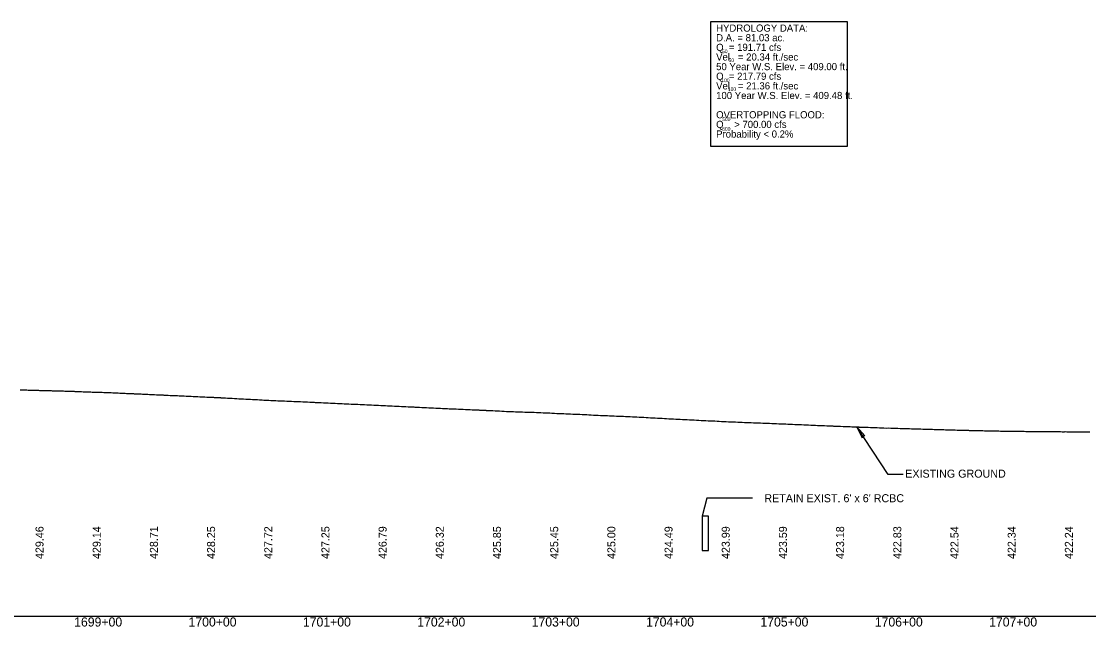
# Model space of a CAD drawing. Extents: x 2017200 to 2047700, y 854850 to 893350.
# Drawn here: x 2024830 to 2025763, y 856091 to 856620 of the extents above; entities that cross this region are included whole.
import ezdxf

# ---------------------------------------------------------------- set-up
doc = ezdxf.new("R2010")
doc.units = 0
for name, color, linetype in [('Culverts', 7, 'Continuous'), ('Default', 7, 'Continuous'), ('RD_DDB_Profile_EX', 7, 'Continuous'), ('RD_DDB_Profile_Lbl', 7, 'Continuous'), ('RD_DDB_StaTX', 7, 'Continuous'), ('RD_DDB_StripGrade', 7, 'Continuous'), ('RD_GPK_Profile_Cell', 7, 'Continuous'), ('RD_PD_DR_Pipe_TX', 7, 'Continuous'), ('RD_PD_Final_TX', 7, 'Continuous')]:
    doc.layers.add(name, color=color, linetype=linetype)

msp = doc.modelspace()

# ---------------------------------------------------------------- linework, layer by layer
at = {"layer": 'Culverts'}
for p, q in [((2025430.37, 856187.4), (2025424.78, 856187.4)), ((2025424.78, 856187.4), (2025424.78, 856157.4)), ((2025430.37, 856157.4), (2025430.37, 856187.4)), ((2025424.78, 856157.4), (2025430.37, 856157.4))]:
    msp.add_line(p, q, dxfattribs=at)
at = {"layer": 'Default'}
msp.add_lwpolyline([(2025432.39, 856620), (2025551.57, 856620), (2025551.57, 856510.68), (2025432.39, 856510.68)], close=True, dxfattribs=at)
at = {"layer": 'RD_DDB_Profile_EX'}
msp.add_lwpolyline([(2024828.51, 856297.92), (2024829.62, 856297.89), (2024830.51, 856297.88), (2024831.62, 856297.85), (2024832.5, 856297.81), (2024833.62, 856297.77), (2024834.5, 856297.76), (2024835.62, 856297.74), (2024836.5, 856297.7), (2024837.62, 856297.66), (2024838.5, 856297.65), (2024839.62, 856297.62), (2024840.5, 856297.59), (2024841.62, 856297.56), (2024842.51, 856297.54), (2024843.62, 856297.51), (2024844.52, 856297.48), (2024845.62, 856297.45), (2024846.54, 856297.44), (2024847.62, 856297.4), (2024848.55, 856297.36), (2024849.61, 856297.33), (2024850.56, 856297.31), (2024851.61, 856297.28), (2024852.56, 856297.25), (2024853.62, 856297.22), (2024854.55, 856297.19), (2024855.62, 856297.19), (2024856.54, 856297.16), (2024857.62, 856297.12), (2024858.53, 856297.12), (2024859.62, 856297.1), (2024860.52, 856297.06), (2024861.62, 856297.03), (2024862.5, 856297.02), (2024863.63, 856297), (2024864.47, 856296.97), (2024865.63, 856296.93), (2024866.45, 856296.91), (2024867.63, 856296.87), (2024868.42, 856296.84), (2024869.64, 856296.79), (2024870.39, 856296.78), (2024871.64, 856296.74), (2024872.37, 856296.7), (2024873.64, 856296.64), (2024874.35, 856296.62), (2024875.65, 856296.59), (2024876.33, 856296.56), (2024877.65, 856296.49), (2024878.31, 856296.48), (2024879.65, 856296.46), (2024880.29, 856296.43), (2024881.65, 856296.35), (2024882.28, 856296.34), (2024883.65, 856296.29), (2024884.29, 856296.26), (2024885.65, 856296.17), (2024886.3, 856296.15), (2024887.65, 856296.13), (2024888.3, 856296.11), (2024889.65, 856296.04), (2024890.31, 856296.02), (2024891.65, 856295.99), (2024892.29, 856295.97), (2024893.66, 856295.9), (2024894.25, 856295.88), (2024895.66, 856295.85), (2024896.21, 856295.83), (2024897.67, 856295.77), (2024898.17, 856295.76), (2024899.67, 856295.73), (2024900.13, 856295.72), (2024901.67, 856295.64), (2024902.11, 856295.62), (2024903.67, 856295.58), (2024904.12, 856295.57), (2024905.67, 856295.5), (2024906.12, 856295.49), (2024907.67, 856295.45), (2024908.12, 856295.43), (2024909.67, 856295.32), (2024910.13, 856295.3), (2024911.67, 856295.24), (2024912.15, 856295.22), (2024913.67, 856295.15), (2024914.19, 856295.13), (2024915.66, 856295.06), (2024916.22, 856295.04), (2024917.66, 856294.99), (2024918.25, 856294.96), (2024919.66, 856294.9), (2024920.28, 856294.88), (2024921.66, 856294.8), (2024922.29, 856294.76), (2024923.66, 856294.72), (2024924.29, 856294.69), (2024925.66, 856294.63), (2024926.29, 856294.6), (2024927.66, 856294.55), (2024928.3, 856294.52), (2024929.66, 856294.45), (2024930.3, 856294.42), (2024931.66, 856294.37), (2024932.27, 856294.34), (2024933.67, 856294.28), (2024934.23, 856294.26), (2024935.67, 856294.23), (2024936.18, 856294.21), (2024937.68, 856294.12), (2024938.13, 856294.1), (2024939.69, 856294.04), (2024940.07, 856294.02), (2024941.69, 856293.92), (2024942.03, 856293.91), (2024943.69, 856293.83), (2024944.05, 856293.8), (2024945.69, 856293.73), (2024946.07, 856293.72), (2024947.68, 856293.65), (2024948.08, 856293.62), (2024949.68, 856293.56), (2024950.1, 856293.54), (2024951.68, 856293.45), (2024952.11, 856293.43), (2024953.68, 856293.38), (2024954.11, 856293.36), (2024955.68, 856293.27), (2024956.12, 856293.25), (2024957.68, 856293.18), (2024958.12, 856293.16), (2024959.68, 856293.07), (2024960.12, 856293.05), (2024961.68, 856293.01), (2024962.12, 856292.99), (2024963.69, 856292.9), (2024964.09, 856292.88), (2024965.69, 856292.82), (2024966.07, 856292.81), (2024967.69, 856292.72), (2024968.05, 856292.7), (2024969.69, 856292.65), (2024970.02, 856292.64), (2024971.7, 856292.53), (2024972.01, 856292.51), (2024973.7, 856292.45), (2024974, 856292.44), (2024975.99, 856292.37), (2024977.98, 856292.26), (2024979.97, 856292.18), (2024981.98, 856292.09), (2024983.7, 856291.99), (2024984.01, 856291.97), (2024985.7, 856291.91), (2024986.03, 856291.9), (2024987.69, 856291.8), (2024988.06, 856291.78), (2024989.69, 856291.73), (2024990.08, 856291.72), (2024991.69, 856291.62), (2024992.1, 856291.59), (2024993.69, 856291.55), (2024994.11, 856291.53), (2024995.69, 856291.45), (2024996.13, 856291.43), (2024997.69, 856291.34), (2024998.14, 856291.32), (2024999.68, 856291.27), (2025000.15, 856291.24), (2025001.69, 856291.16), (2025002.14, 856291.14), (2025003.69, 856291.06), (2025004.11, 856291.04), (2025005.69, 856290.94), (2025006.08, 856290.93), (2025007.7, 856290.84), (2025008.04, 856290.82), (2025010, 856290.72), (2025011.97, 856290.59), (2025013.96, 856290.47), (2025015.94, 856290.37), (2025017.92, 856290.3), (2025019.9, 856290.14), (2025021.91, 856290.04), (2025023.94, 856289.92), (2025025.97, 856289.84), (2025027.99, 856289.75), (2025029.7, 856289.63), (2025030.02, 856289.62), (2025031.7, 856289.53), (2025032.04, 856289.52), (2025033.7, 856289.43), (2025034.06, 856289.41), (2025035.7, 856289.33), (2025036.08, 856289.31), (2025037.7, 856289.21), (2025038.1, 856289.19), (2025039.69, 856289.11), (2025040.12, 856289.09), (2025041.7, 856289), (2025042.11, 856288.97), (2025043.7, 856288.9), (2025044.09, 856288.88), (2025045.7, 856288.8), (2025046.07, 856288.79), (2025047.7, 856288.71), (2025048.05, 856288.69), (2025049.71, 856288.61), (2025050.03, 856288.59), (2025052, 856288.49), (2025053.96, 856288.41), (2025055.92, 856288.32), (2025057.87, 856288.27), (2025059.83, 856288.15), (2025061.81, 856288.1), (2025063.8, 856287.99), (2025065.79, 856287.93), (2025067.79, 856287.83), (2025069.78, 856287.77), (2025071.78, 856287.67), (2025073.78, 856287.6), (2025075.79, 856287.47), (2025077.79, 856287.41), (2025079.79, 856287.31), (2025081.78, 856287.21), (2025083.77, 856287.08), (2025085.75, 856286.99), (2025086.4, 856286.95), (2025087.75, 856286.87), (2025089.75, 856286.79), (2025091.79, 856286.68), (2025093.83, 856286.59), (2025095.88, 856286.47), (2025097.91, 856286.44), (2025099.95, 856286.27), (2025101.97, 856286.24), (2025103.98, 856286.15), (2025105.99, 856286.08), (2025108, 856285.97), (2025110.01, 856285.91), (2025112, 856285.77), (2025113.98, 856285.7), (2025115.96, 856285.6), (2025117.94, 856285.51), (2025119.93, 856285.43), (2025121.9, 856285.31), (2025123.87, 856285.25), (2025125.84, 856285.13), (2025127.8, 856285.08), (2025129.77, 856284.94), (2025131.79, 856284.86), (2025133.81, 856284.7), (2025135.84, 856284.66), (2025137.86, 856284.56), (2025139.88, 856284.5), (2025141.88, 856284.38), (2025143.88, 856284.29), (2025145.87, 856284.13), (2025147.86, 856284.08), (2025149.86, 856283.97), (2025151.83, 856283.9), (2025153.79, 856283.86), (2025155.76, 856283.72), (2025156.33, 856283.7), (2025157.81, 856283.64), (2025159.89, 856283.53), (2025161.89, 856283.46), (2025163.88, 856283.33), (2025165.87, 856283.27), (2025167.86, 856283.15), (2025169.85, 856283.07), (2025171.78, 856282.96), (2025172.68, 856282.9), (2025173.77, 856282.84), (2025175.79, 856282.76), (2025177.82, 856282.68), (2025179.85, 856282.59), (2025181.82, 856282.44), (2025183.8, 856282.35), (2025185.77, 856282.26), (2025187.46, 856282.17), (2025187.76, 856282.15), (2025189.83, 856282.05), (2025191.89, 856281.95), (2025193.96, 856281.87), (2025196.02, 856281.74), (2025197.72, 856281.68), (2025198.07, 856281.66), (2025199.71, 856281.59), (2025200.11, 856281.58), (2025201.72, 856281.53), (2025202.07, 856281.52), (2025203.72, 856281.43), (2025204.03, 856281.42), (2025205.98, 856281.35), (2025207.94, 856281.23), (2025209.89, 856281.15), (2025211.91, 856281.04), (2025213.94, 856280.97), (2025215.96, 856280.88), (2025217.97, 856280.79), (2025220, 856280.71), (2025221.72, 856280.66), (2025222.04, 856280.65), (2025223.72, 856280.55), (2025224.09, 856280.53), (2025225.72, 856280.46), (2025226.13, 856280.44), (2025227.71, 856280.36), (2025228.17, 856280.33), (2025229.71, 856280.28), (2025230.19, 856280.25), (2025231.71, 856280.17), (2025232.15, 856280.15), (2025233.72, 856280.1), (2025234.11, 856280.08), (2025235.72, 856279.99), (2025236.07, 856279.97), (2025238.03, 856279.9), (2025239.98, 856279.79), (2025241.91, 856279.69), (2025243.84, 856279.59), (2025246, 856279.48), (2025247.78, 856279.41), (2025249.81, 856279.25), (2025251.81, 856279.2), (2025253.82, 856279.07), (2025255.82, 856278.99), (2025257.82, 856278.88), (2025259.82, 856278.85), (2025261.8, 856278.77), (2025263.78, 856278.72), (2025265.76, 856278.62), (2025266.5, 856278.6), (2025267.79, 856278.58), (2025269.83, 856278.49), (2025271.87, 856278.45), (2025273.91, 856278.36), (2025275.94, 856278.31), (2025277.98, 856278.23), (2025279.99, 856278.14), (2025281.97, 856278.07), (2025283.95, 856278), (2025285.93, 856277.92), (2025287.91, 856277.84), (2025289.87, 856277.71), (2025291.82, 856277.65), (2025293.52, 856277.53), (2025295.79, 856277.44), (2025297.82, 856277.32), (2025299.83, 856277.27), (2025301.82, 856277.17), (2025303.82, 856277.1), (2025305.81, 856276.98), (2025307.81, 856276.88), (2025309.79, 856276.82), (2025311.78, 856276.75), (2025313.09, 856276.7), (2025313.78, 856276.67), (2025315.82, 856276.58), (2025317.86, 856276.51), (2025319.89, 856276.4), (2025321.9, 856276.32), (2025323.92, 856276.19), (2025325.93, 856276.13), (2025327.95, 856275.99), (2025329.96, 856275.89), (2025331.96, 856275.78), (2025333.96, 856275.71), (2025335.97, 856275.59), (2025337.97, 856275.52), (2025339.98, 856275.4), (2025341.98, 856275.33), (2025343.99, 856275.22), (2025345.99, 856275.15), (2025347.99, 856275.04), (2025349.99, 856274.99), (2025351.99, 856274.91), (2025353.98, 856274.83), (2025355.98, 856274.77), (2025357.98, 856274.67), (2025359.96, 856274.59), (2025361.94, 856274.48), (2025363.93, 856274.37), (2025365.91, 856274.25), (2025367.89, 856274.17), (2025369.86, 856274.05), (2025371.84, 856274.01), (2025373.81, 856273.87), (2025375.78, 856273.77), (2025376.65, 856273.71), (2025377.78, 856273.64), (2025379.79, 856273.55), (2025381.8, 856273.44), (2025383.8, 856273.35), (2025385.81, 856273.25), (2025387.82, 856273.13), (2025389.82, 856273.03), (2025391.82, 856272.89), (2025393.83, 856272.74), (2025395.83, 856272.65), (2025397.83, 856272.54), (2025399.82, 856272.44), (2025401.81, 856272.33), (2025403.8, 856272.23), (2025405.79, 856272.15), (2025407.78, 856272.04), (2025408.16, 856272.02), (2025409.8, 856271.94), (2025411.83, 856271.86), (2025413.87, 856271.78), (2025415.9, 856271.63), (2025417.93, 856271.55), (2025419.95, 856271.41), (2025421.96, 856271.33), (2025423.98, 856271.22), (2025425.99, 856271.12), (2025428.01, 856271.03), (2025430, 856270.92), (2025431.98, 856270.84), (2025433.96, 856270.75), (2025435.94, 856270.66), (2025437.92, 856270.53), (2025439.86, 856270.46), (2025441.89, 856270.32), (2025443.81, 856270.27), (2025445.85, 856270.12), (2025447.88, 856270.06), (2025449.9, 856269.93), (2025451.91, 856269.9), (2025453.92, 856269.78), (2025455.93, 856269.74), (2025457.94, 856269.6), (2025459.93, 856269.58), (2025461.92, 856269.46), (2025463.9, 856269.28), (2025465.88, 856269.21), (2025467.87, 856269.21), (2025469.86, 856269.13), (2025471.84, 856269.09), (2025473.83, 856268.99), (2025475.81, 856268.93), (2025477.8, 856268.85), (2025479.81, 856268.75), (2025481.82, 856268.67), (2025483.83, 856268.62), (2025485.85, 856268.56), (2025487.86, 856268.43), (2025489.87, 856268.37), (2025491.87, 856268.29), (2025493.88, 856268.21), (2025495.89, 856268.11), (2025497.9, 856268.03), (2025499.89, 856267.97), (2025501.88, 856267.88), (2025503.87, 856267.8), (2025505.86, 856267.71), (2025507.85, 856267.65), (2025509.84, 856267.53), (2025511.82, 856267.47), (2025513.81, 856267.35), (2025515.79, 856267.34), (2025516.27, 856267.31), (2025517.81, 856267.21), (2025519.82, 856267.15), (2025521.83, 856267.03), (2025523.84, 856266.96), (2025525.85, 856266.8), (2025527.86, 856266.76), (2025529.84, 856266.68), (2025531.82, 856266.62), (2025534.01, 856266.56), (2025535.8, 856266.43), (2025537.81, 856266.36), (2025538.99, 856266.3), (2025539.81, 856266.26), (2025541.87, 856266.21), (2025543.92, 856266.1), (2025545.97, 856266.04), (2025548.02, 856265.95), (2025550.06, 856265.89), (2025551.76, 856265.82), (2025552.1, 856265.8), (2025553.76, 856265.74), (2025554.14, 856265.73), (2025555.76, 856265.63), (2025556.17, 856265.61), (2025557.76, 856265.53), (2025558.2, 856265.52), (2025559.76, 856265.47), (2025560.18, 856265.46), (2025561.76, 856265.41), (2025562.16, 856265.39), (2025563.76, 856265.33), (2025564.14, 856265.32), (2025565.77, 856265.27), (2025566.11, 856265.25), (2025567.77, 856265.19), (2025568.09, 856265.18), (2025570.06, 856265.12), (2025572.03, 856265.09), (2025574, 856265), (2025575.97, 856264.94), (2025577.94, 856264.84), (2025579.91, 856264.79), (2025581.88, 856264.65), (2025583.85, 856264.65), (2025585.82, 856264.53), (2025587.81, 856264.54), (2025589.84, 856264.41), (2025591.87, 856264.42), (2025593.9, 856264.35), (2025595.92, 856264.31), (2025597.95, 856264.19), (2025600, 856264.15), (2025602.04, 856264.08), (2025603.77, 856264.04), (2025604.08, 856264.03), (2025605.77, 856263.98), (2025606.11, 856263.97), (2025607.77, 856263.93), (2025608.14, 856263.92), (2025609.77, 856263.87), (2025610.16, 856263.85), (2025611.77, 856263.8), (2025612.18, 856263.79), (2025613.77, 856263.75), (2025614.19, 856263.73), (2025615.76, 856263.7), (2025616.21, 856263.69), (2025617.76, 856263.62), (2025618.22, 856263.6), (2025619.76, 856263.56), (2025620.22, 856263.55), (2025621.76, 856263.5), (2025622.22, 856263.48), (2025623.77, 856263.46), (2025624.21, 856263.45), (2025625.77, 856263.38), (2025626.21, 856263.37), (2025627.77, 856263.33), (2025628.21, 856263.32), (2025629.77, 856263.26), (2025630.2, 856263.25), (2025631.77, 856263.21), (2025632.19, 856263.2), (2025633.77, 856263.16), (2025634.17, 856263.15), (2025635.77, 856263.11), (2025636.16, 856263.1), (2025637.77, 856263.04), (2025638.15, 856263.03), (2025639.77, 856262.97), (2025640.14, 856262.96), (2025641.78, 856262.92), (2025642.13, 856262.9), (2025643.78, 856262.84), (2025644.12, 856262.83), (2025645.78, 856262.81), (2025646.11, 856262.8), (2025647.78, 856262.73), (2025648.11, 856262.72), (2025649.78, 856262.69), (2025650.13, 856262.68), (2025651.78, 856262.58), (2025652.15, 856262.57), (2025653.77, 856262.6), (2025654.17, 856262.59), (2025655.77, 856262.54), (2025656.19, 856262.53), (2025657.77, 856262.5), (2025658.21, 856262.49), (2025659.77, 856262.44), (2025660.23, 856262.42), (2025661.77, 856262.39), (2025662.25, 856262.37), (2025663.77, 856262.35), (2025664.28, 856262.34), (2025665.77, 856262.32), (2025666.3, 856262.3), (2025667.76, 856262.29), (2025668.31, 856262.28), (2025669.77, 856262.25), (2025670.3, 856262.23), (2025671.77, 856262.19), (2025672.3, 856262.18), (2025673.77, 856262.14), (2025674.29, 856262.13), (2025675.77, 856262.09), (2025676.29, 856262.09), (2025677.77, 856262.05), (2025678.27, 856262.04), (2025679.77, 856262), (2025680.24, 856261.99), (2025681.78, 856261.98), (2025682.2, 856261.97), (2025683.78, 856261.93), (2025684.16, 856261.92), (2025685.78, 856261.89), (2025686.13, 856261.88), (2025687.78, 856261.84), (2025688.12, 856261.83), (2025689.78, 856261.8), (2025690.14, 856261.79), (2025691.78, 856261.73), (2025692.17, 856261.73), (2025693.78, 856261.72), (2025694.19, 856261.71), (2025695.78, 856261.7), (2025696.21, 856261.7), (2025697.78, 856261.71), (2025698.24, 856261.71), (2025699.77, 856261.71), (2025700.27, 856261.71), (2025701.77, 856261.7), (2025702.3, 856261.68), (2025703.77, 856261.66), (2025704.33, 856261.65), (2025705.77, 856261.63), (2025706.36, 856261.62), (2025707.77, 856261.61), (2025708.36, 856261.6), (2025709.77, 856261.6), (2025710.34, 856261.6), (2025711.77, 856261.58), (2025712.32, 856261.58), (2025713.77, 856261.56), (2025714.3, 856261.53), (2025715.78, 856261.5), (2025716.28, 856261.52), (2025717.78, 856261.53), (2025718.26, 856261.53), (2025719.78, 856261.49), (2025720.25, 856261.48), (2025721.78, 856261.48), (2025722.23, 856261.47), (2025723.78, 856261.44), (2025724.22, 856261.44), (2025725.78, 856261.45), (2025726.2, 856261.45), (2025727.78, 856261.4), (2025728.19, 856261.4), (2025729.79, 856261.41), (2025730.18, 856261.41), (2025731.79, 856261.39), (2025732.18, 856261.39), (2025733.79, 856261.4), (2025734.17, 856261.4), (2025735.79, 856261.34), (2025736.16, 856261.34), (2025737.79, 856261.35), (2025738.16, 856261.35), (2025739.79, 856261.32), (2025740.16, 856261.31), (2025741.79, 856261.32), (2025742.17, 856261.33), (2025743.79, 856261.29), (2025744.17, 856261.28), (2025745.79, 856261.27), (2025746.18, 856261.27), (2025747.79, 856261.25), (2025748.19, 856261.24), (2025749.79, 856261.21), (2025750.22, 856261.22), (2025751.79, 856261.21), (2025752.24, 856261.2), (2025753.78, 856261.2), (2025754.26, 856261.2), (2025755.78, 856261.17), (2025756.28, 856261.16), (2025757.78, 856261.12), (2025758.3, 856261.12), (2025759.78, 856261.12), (2025760.32, 856261.11), (2025761.78, 856261.09), (2025762.34, 856261.08), (2025763.78, 856261.09)], dxfattribs=at)
at = {"layer": 'RD_DDB_Profile_Lbl'}
for p, q in [((2025587.64, 856223.74), (2025560.18, 856265.46)), ((2025600.5, 856223.74), (2025587.64, 856223.74))]:
    msp.add_line(p, q, dxfattribs=at)
msp.add_lwpolyline([(2025560.18, 856265.46), (2025564.64, 856255.96), (2025565.01, 856258.12), (2025567.14, 856257.6)], close=True, dxfattribs=at)
at = {"layer": 'RD_GPK_Profile_Cell'}
msp.add_line((2020500, 856100), (2047700, 856100), dxfattribs=at)
at = {"layer": 'RD_PD_DR_Pipe_TX'}
for p, q in [((2025429, 856203.15), (2025424.78, 856187.4)), ((2025469, 856203.15), (2025429, 856203.15))]:
    msp.add_line(p, q, dxfattribs=at)

# ---------------------------------------------------------------- texts
at = {"layer": 'RD_DDB_Profile_Lbl'}
msp.add_text('EXISTING GROUND', height=7, dxfattribs=at).set_placement((2025602.44, 856221.12))
at = {"layer": 'RD_DDB_StaTX'}
for s, p in [('1699+00', (2024875.8, 856091)), ('1700+00', (2024975.8, 856091)), ('1701+00', (2025075.8, 856091)), ('1702+00', (2025175.8, 856091)), ('1703+00', (2025275.8, 856091)), ('1704+00', (2025375.8, 856091)), ('1705+00', (2025475.8, 856091)), ('1706+00', (2025575.8, 856091)), ('1707+00', (2025675.8, 856091))]:
    msp.add_text(s, height=8, dxfattribs=at).set_placement(p)
at = {"layer": 'RD_DDB_StripGrade'}
for s, p in [('429.46', (2024849, 856150)), ('429.14', (2024899, 856150)), ('428.71', (2024949, 856150)), ('428.25', (2024999, 856150)), ('427.72', (2025049, 856150)), ('427.25', (2025099, 856150)), ('426.79', (2025149, 856150)), ('426.32', (2025199, 856150)), ('425.85', (2025249, 856150)), ('425.45', (2025299, 856150)), ('425.00', (2025349, 856150)), ('424.49', (2025399, 856150)), ('423.99', (2025449, 856150)), ('423.59', (2025499, 856150)), ('423.18', (2025549, 856150)), ('422.83', (2025599, 856150)), ('422.54', (2025649, 856150)), ('422.34', (2025699, 856150)), ('422.24', (2025749, 856150))]:
    msp.add_text(s, height=7, rotation=90, dxfattribs=at).set_placement(p)
at = {"layer": 'RD_PD_DR_Pipe_TX'}
msp.add_text("RETAIN EXIST. 6' x 6' RCBC", height=7, dxfattribs=at).set_placement((2025479.24, 856199.65))
at = {"layer": 'RD_PD_Final_TX'}
for s, height, p in [('HYDROLOGY DATA:', 6.25, (2025437.1, 856610.99)), ('D.A. = 81.03 ac.', 6.25, (2025437.1, 856602.58)), ('Q  = 191.71 cfs', 6.25, (2025437.1, 856594.16)), ('Vel   = 20.34 ft./sec', 6.25, (2025437.1, 856585.74)), ('50', 3.125, (2025442.24, 856592.2)), ('50 Year W.S. Elev. = 409.00 ft.', 6.25, (2025437.1, 856577.32)), ('50', 3.125, (2025447.98, 856584.43)), ('Q  = 217.79 cfs', 6.25, (2025437.1, 856568.9)), ('Vel   = 21.36 ft./sec', 6.25, (2025437.1, 856560.48)), ('100', 3.125, (2025441.64, 856566.86)), ('100', 3.125, (2025447.36, 856559.2)), ('100 Year W.S. Elev. = 409.48 ft.', 6.25, (2025437.1, 856552.07)), ('OVERTOPPING FLOOD:', 6.25, (2025437.1, 856535.23)), ('500', 3.125, (2025442.39, 856532.85)), ('Q    > 700.00 cfs', 6.25, (2025437.1, 856526.81)), ('Probability < 0.2%', 6.25, (2025437.1, 856518.39)), ('500', 3.125, (2025442.39, 856524.44))]:
    msp.add_text(s, height=height, rotation=360, dxfattribs=at).set_placement(p)

doc.saveas('drawing.dxf')
